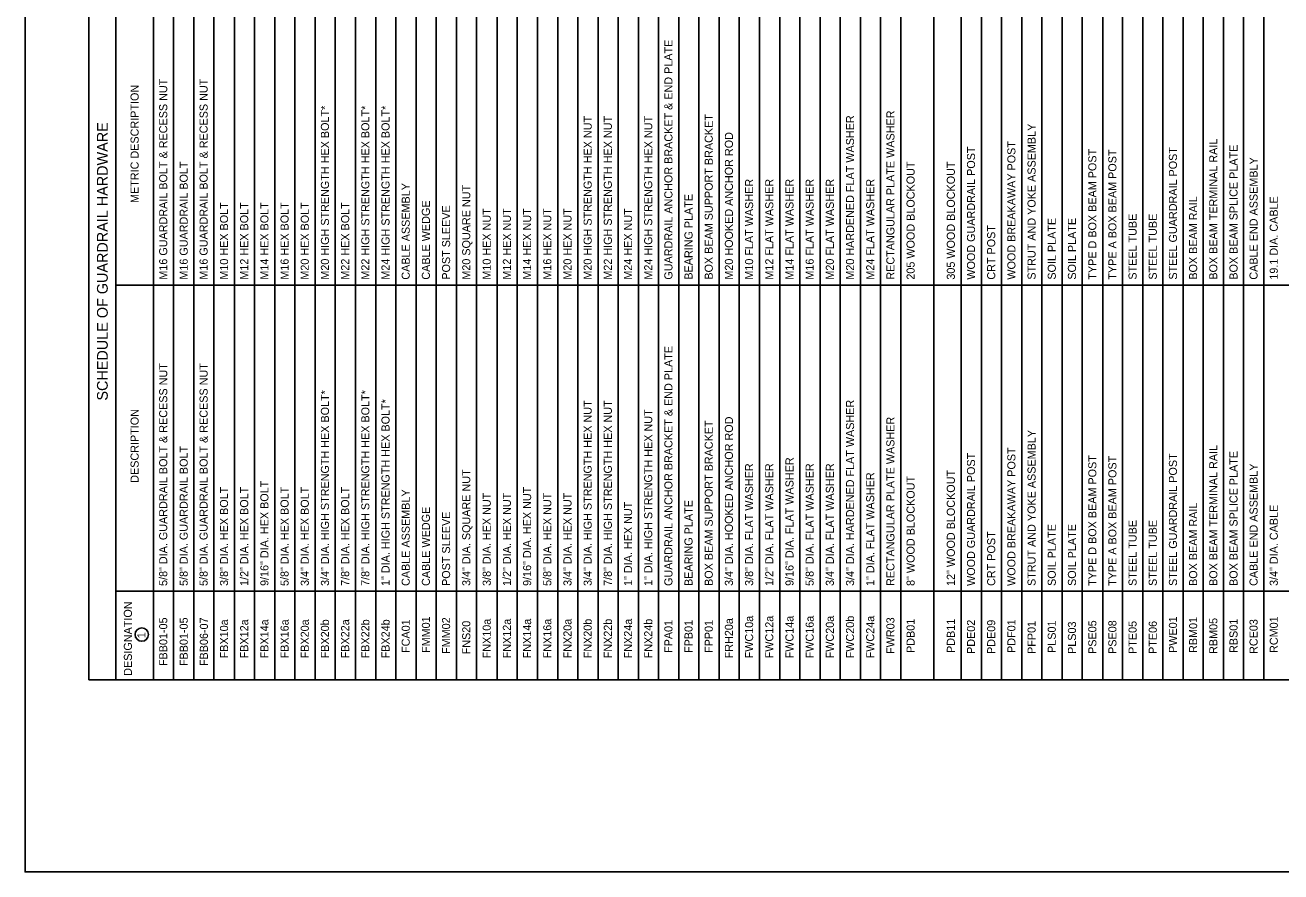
# Model space of a CAD drawing. Extents: x 49991.4 to 50021, y 49987.6 to 50011.4.
# Drawn here: x 49999.38 to 50008.71, y 49987.8 to 49994.09 of the extents above; entities that cross this region are included whole.
import ezdxf

# ---------------------------------------------------------------- set-up
doc = ezdxf.new("R2010")
doc.units = 0
doc.layers.add('Level 1', color=7, linetype='Continuous')
doc.layers.add('Level 2', color=7, linetype='Continuous')

msp = doc.modelspace()

# ---------------------------------------------------------------- linework, layer by layer
at = {"layer": 'Level 1'}
msp.add_lwpolyline([(49999.3755, 49998.9992), (50016.7421, 49998.9992), (50016.7421, 49987.7988), (49999.3755, 49987.7988)], close=True, dxfattribs=at)
at = {"layer": 'Level 2'}
for p, q in [((49999.8495, 49989.2267), (49999.8495, 49998.6426)), ((50000.3287, 49989.2267), (50000.3287, 49998.6426)), ((50000.4787, 49989.2267), (50000.4787, 49998.6426)), ((50000.6287, 49989.2267), (50000.6287, 49998.6426)), ((50000.7787, 49989.2267), (50000.7787, 49998.6426)), ((50000.9304, 49989.2267), (50000.9304, 49998.6426)), ((50001.0804, 49989.2267), (50001.0804, 49998.6426)), ((50001.2304, 49989.2267), (50001.2304, 49998.6426)), ((50001.3804, 49989.2267), (50001.3804, 49998.6426)), ((50001.5304, 49989.2267), (50001.5304, 49998.6426)), ((50001.6804, 49989.2267), (50001.6804, 49998.6426)), ((50001.8304, 49989.2267), (50001.8304, 49998.6426)), ((50001.9804, 49989.2267), (50001.9804, 49998.6426)), ((50002.1304, 49989.2267), (50002.1304, 49998.6426)), ((50002.2804, 49989.2267), (50002.2804, 49998.6426)), ((50002.4304, 49989.2267), (50002.4304, 49998.6426)), ((50002.5804, 49989.2267), (50002.5804, 49998.6426)), ((50002.7304, 49989.2267), (50002.7304, 49998.6426)), ((50002.8826, 49989.2267), (50002.8826, 49998.6426)), ((50003.0326, 49989.2267), (50003.0326, 49998.6426)), ((50003.1826, 49989.2267), (50003.1826, 49998.6426)), ((50003.3326, 49989.2267), (50003.3326, 49998.6426)), ((50003.4826, 49989.2267), (50003.4826, 49998.6426)), ((50003.6326, 49989.2267), (50003.6326, 49998.6426)), ((50003.7826, 49989.2267), (50003.7826, 49998.6426)), ((50003.9326, 49989.2267), (50003.9326, 49998.6426)), ((50004.0826, 49989.2267), (50004.0826, 49998.6426)), ((50004.2326, 49989.2267), (50004.2326, 49998.6426)), ((50004.3822, 49989.2267), (50004.3822, 49998.6426)), ((50004.5322, 49989.2267), (50004.5322, 49998.6426)), ((50004.6822, 49989.2267), (50004.6822, 49998.6426)), ((50004.8322, 49989.2267), (50004.8322, 49998.6426)), ((50004.9822, 49989.2267), (50004.9822, 49998.6426)), ((50005.1322, 49989.2267), (50005.1322, 49998.6426)), ((50005.2822, 49989.2267), (50005.2822, 49998.6426)), ((50005.4322, 49989.2267), (50005.4322, 49998.6426)), ((50005.5822, 49989.2267), (50005.5822, 49998.6426)), ((50005.7322, 49989.2267), (50005.7322, 49998.6426)), ((50005.8822, 49989.2267), (50005.8822, 49998.6426)), ((50006.1277, 49989.2267), (50006.1277, 49998.6426)), ((50006.3311, 49989.2267), (50006.3311, 49998.6426)), ((50006.4811, 49989.2267), (50006.4811, 49998.6426)), ((50006.6311, 49989.2267), (50006.6311, 49998.6426)), ((50006.7811, 49989.2267), (50006.7811, 49998.6426)), ((50006.9311, 49989.2267), (50006.9311, 49998.6426)), ((50007.0811, 49989.2267), (50007.0811, 49998.6426)), ((50007.2311, 49989.2267), (50007.2311, 49998.6426)), ((50007.3826, 49989.2267), (50007.3826, 49998.6426)), ((50007.5295, 49989.2267), (50007.5295, 49998.6426)), ((50007.6795, 49989.2267), (50007.6795, 49998.6426)), ((50007.8295, 49989.2267), (50007.8295, 49998.6426)), ((50007.9795, 49989.2267), (50007.9795, 49998.6426)), ((50008.1295, 49989.2267), (50008.1295, 49998.6426)), ((50008.2795, 49989.2267), (50008.2795, 49998.6426)), ((50008.4295, 49989.2267), (50008.4295, 49998.6426)), ((50008.5786, 49989.2267), (50008.5786, 49998.6426)), ((49999.8495, 49989.2267), (49999.8495, 49997.4312)), ((50000.0495, 49989.2267), (50000.0495, 49995.6426)), ((50000.0495, 49992.1605), (50013.2892, 49992.1605)), ((50013.2892, 49989.8841), (50000.0495, 49989.8841)), ((49999.8495, 49989.2267), (50013.2892, 49989.2267)), ((50000.6287, 49989.2267), (50000.4787, 49989.2267))]:
    msp.add_line(p, q, dxfattribs=at)
msp.add_circle((50000.2422, 49989.5627), 0.05, dxfattribs=at)

# ---------------------------------------------------------------- texts
for s, height, p in [('GUARDRAIL ANCHOR BRACKET & END PLATE', 0.06, (50004.1854, 49992.2005)), ('M16 GUARDRAIL BOLT & RECESS NUT', 0.06, (50000.4317, 49992.2004)), ('M16 GUARDRAIL BOLT & RECESS NUT', 0.06, (50000.7317, 49992.2004)), ('METRIC DESCRIPTION', 0.06, (50000.2191, 49992.7705)), ('M20 HIGH STRENGTH HEX BOLT*', 0.06, (50001.6334, 49992.2004)), ('M22 HIGH STRENGTH HEX BOLT*', 0.06, (50001.9334, 49992.2004)), ('M24 HIGH STRENGTH HEX BOLT*', 0.06, (50002.0834, 49992.2004)), ('M20 HIGH STRENGTH HEX NUT', 0.06, (50003.5854, 49992.2005)), ('M22 HIGH STRENGTH HEX NUT', 0.06, (50003.7354, 49992.2005)), ('M24 HIGH STRENGTH HEX NUT', 0.06, (50004.0354, 49992.2005)), ('BOX BEAM SUPPORT BRACKET', 0.06, (50004.485, 49992.2005)), ('M20 HARDENED FLAT WASHER', 0.06, (50005.535, 49992.2005)), ('RECTANGULAR PLATE WASHER', 0.06, (50005.835, 49992.2005)), ('SCHEDULE OF GUARDRAIL HARDWARE', 0.08, (49999.9895, 49991.3018)), ('M20 HOOKED ANCHOR ROD', 0.06, (50004.635, 49992.2005)), ('STRUT AND YOKE ASSEMBLY', 0.06, (50006.8839, 49992.2005)), ('WOOD BREAKAWAY POST', 0.06, (50006.7339, 49992.2005)), ('BOX BEAM TERMINAL RAIL', 0.06, (50008.2344, 49992.2005)), ('BOX BEAM SPLICE PLATE', 0.06, (50008.3844, 49992.2005)), ('WOOD GUARDRAIL POST', 0.06, (50006.4339, 49992.2005)), ('TYPE D BOX BEAM POST', 0.06, (50007.3354, 49992.2005)), ('TYPE A BOX BEAM POST', 0.06, (50007.4844, 49992.2005)), ('STEEL GUARDRAIL POST', 0.06, (50007.9344, 49992.2005)), ('CABLE END ASSEMBLY', 0.06, (50008.5335, 49992.2005)), ('M16 GUARDRAIL BOLT', 0.06, (50000.5837, 49992.2004)), ('205 WOOD BLOCKOUT', 0.06, (50005.985, 49992.2005)), ('305 WOOD BLOCKOUT', 0.06, (50006.2839, 49992.2005)), ('CABLE ASSEMBLY', 0.06, (50002.2334, 49992.2004)), ('M10 FLAT WASHER', 0.06, (50004.785, 49992.2005)), ('M12 FLAT WASHER', 0.06, (50004.935, 49992.2005)), ('M14 FLAT WASHER', 0.06, (50005.085, 49992.2005)), ('M16 FLAT WASHER', 0.06, (50005.235, 49992.2005)), ('M20 FLAT WASHER', 0.06, (50005.385, 49992.2005)), ('M24 FLAT WASHER', 0.06, (50005.685, 49992.2005)), ('M20 SQUARE NUT', 0.06, (50002.6834, 49992.2004)), ('BEARING PLATE', 0.06, (50004.335, 49992.2005)), ('M10 HEX BOLT', 0.06, (50000.8834, 49992.2004)), ('M12 HEX BOLT', 0.06, (50001.0334, 49992.2004)), ('M14 HEX BOLT', 0.06, (50001.1834, 49992.2004)), ('M16 HEX BOLT', 0.06, (50001.3334, 49992.2004)), ('M20 HEX BOLT', 0.06, (50001.4834, 49992.2004)), ('M22 HEX BOLT', 0.06, (50001.7834, 49992.2004)), ('CABLE WEDGE', 0.06, (50002.3834, 49992.2004)), ('POST SLEEVE', 0.06, (50002.5334, 49992.2004)), ('M10 HEX NUT', 0.06, (50002.8354, 49992.2005)), ('M12 HEX NUT', 0.06, (50002.9854, 49992.2005)), ('M14 HEX NUT', 0.06, (50003.1354, 49992.2005)), ('M16 HEX NUT', 0.06, (50003.2854, 49992.2005)), ('M20 HEX NUT', 0.06, (50003.4354, 49992.2005)), ('M24 HEX NUT', 0.06, (50003.8854, 49992.2005)), ('BOX BEAM RAIL', 0.06, (50008.0844, 49992.2005)), ('19.1 DIA. CABLE', 0.06, (50008.6835, 49992.2005)), ('SOIL PLATE', 0.06, (50007.0339, 49992.2005)), ('SOIL PLATE', 0.06, (50007.1839, 49992.2005)), ('STEEL TUBE', 0.06, (50007.6344, 49992.2005)), ('STEEL TUBE', 0.06, (50007.7844, 49992.2005)), ('CRT POST', 0.06, (50006.5839, 49992.2005)), ('GUARDRAIL ANCHOR BRACKET & END PLATE', 0.06, (50004.1854, 49989.9241)), ('5/8" DIA. GUARDRAIL BOLT & RECESS NUT', 0.06, (50000.4317, 49989.924)), ('5/8" DIA. GUARDRAIL BOLT & RECESS NUT', 0.06, (50000.7317, 49989.924)), ('3/4" DIA. HIGH STRENGTH HEX BOLT*', 0.06, (50001.6334, 49989.924)), ('7/8" DIA. HIGH STRENGTH HEX BOLT*', 0.06, (50001.9334, 49989.924)), ('1" DIA. HIGH STRENGTH HEX BOLT*', 0.06, (50002.0834, 49989.924)), ('3/4" DIA. HIGH STRENGTH HEX NUT', 0.06, (50003.5854, 49989.9241)), ('7/8" DIA. HIGH STRENGTH HEX NUT', 0.06, (50003.7354, 49989.9241)), ('1" DIA. HIGH STRENGTH HEX NUT', 0.06, (50004.0354, 49989.9241)), ('3/4" DIA. HARDENED FLAT WASHER', 0.06, (50005.535, 49989.9241)), ('DESCRIPTION', 0.06, (50000.2191, 49990.6907)), ('BOX BEAM SUPPORT BRACKET', 0.06, (50004.485, 49989.9241)), ('3/4" DIA. HOOKED ANCHOR ROD', 0.06, (50004.635, 49989.9241)), ('RECTANGULAR PLATE WASHER', 0.06, (50005.835, 49989.9241)), ('STRUT AND YOKE ASSEMBLY', 0.06, (50006.8839, 49989.9241)), ('5/8" DIA. GUARDRAIL BOLT', 0.06, (50000.5837, 49989.924)), ('BOX BEAM TERMINAL RAIL', 0.06, (50008.2344, 49989.9241)), ('9/16" DIA. FLAT WASHER', 0.06, (50005.085, 49989.9241)), ('WOOD GUARDRAIL POST', 0.06, (50006.4339, 49989.9241)), ('WOOD BREAKAWAY POST', 0.06, (50006.7339, 49989.9241)), ('TYPE D BOX BEAM POST', 0.06, (50007.3354, 49989.9241)), ('TYPE A BOX BEAM POST', 0.06, (50007.4844, 49989.9241)), ('STEEL GUARDRAIL POST', 0.06, (50007.9344, 49989.9241)), ('BOX BEAM SPLICE PLATE', 0.06, (50008.3844, 49989.9241)), ('3/4" DIA. SQUARE NUT', 0.06, (50002.6834, 49989.924)), ('3/8" DIA. FLAT WASHER', 0.06, (50004.785, 49989.9241)), ('1/2" DIA. FLAT WASHER', 0.06, (50004.935, 49989.9241)), ('5/8" DIA. FLAT WASHER', 0.06, (50005.235, 49989.9241)), ('3/4" DIA. FLAT WASHER', 0.06, (50005.385, 49989.9241)), ('12" WOOD BLOCKOUT', 0.06, (50006.2839, 49989.9241)), ('CABLE END ASSEMBLY', 0.06, (50008.5335, 49989.9241)), ('9/16" DIA. HEX BOLT', 0.06, (50001.1834, 49989.924)), ('1" DIA. FLAT WASHER', 0.06, (50005.685, 49989.9241)), ('8" WOOD BLOCKOUT', 0.06, (50005.985, 49989.9241)), ('3/8" DIA. HEX BOLT', 0.06, (50000.8834, 49989.924)), ('1/2" DIA. HEX BOLT', 0.06, (50001.0334, 49989.924)), ('5/8" DIA. HEX BOLT', 0.06, (50001.3334, 49989.924)), ('3/4" DIA. HEX BOLT', 0.06, (50001.4834, 49989.924)), ('7/8" DIA. HEX BOLT', 0.06, (50001.7834, 49989.924)), ('CABLE ASSEMBLY', 0.06, (50002.2334, 49989.924)), ('3/8" DIA. HEX NUT', 0.06, (50002.8354, 49989.9241)), ('1/2" DIA. HEX NUT', 0.06, (50002.9854, 49989.9241)), ('9/16" DIA. HEX NUT', 0.06, (50003.1354, 49989.9241)), ('5/8" DIA. HEX NUT', 0.06, (50003.2854, 49989.9241)), ('3/4" DIA. HEX NUT', 0.06, (50003.4354, 49989.9241)), ('CABLE WEDGE', 0.06, (50002.3834, 49989.924)), ('1" DIA. HEX NUT', 0.06, (50003.8854, 49989.9241)), ('BEARING PLATE', 0.06, (50004.335, 49989.9241)), ('BOX BEAM RAIL', 0.06, (50008.0844, 49989.9241)), ('3/4" DIA. CABLE', 0.06, (50008.6835, 49989.9241)), ('POST SLEEVE', 0.06, (50002.5334, 49989.924)), ('STEEL TUBE', 0.06, (50007.6344, 49989.9241)), ('STEEL TUBE', 0.06, (50007.7844, 49989.9241)), ('CRT POST', 0.06, (50006.5839, 49989.9241)), ('SOIL PLATE', 0.06, (50007.0339, 49989.9241)), ('SOIL PLATE', 0.06, (50007.1839, 49989.9241)), ('DESIGNATION', 0.06, (50000.1691, 49989.2562)), ('FBB01-05', 0.06, (50000.4317, 49989.3287)), ('FBB01-05', 0.06, (50000.5837, 49989.3287)), ('FBB06-07', 0.06, (50000.7337, 49989.3287)), ('FBX10a', 0.06, (50000.8834, 49989.3859)), ('FBX12a', 0.06, (50001.0334, 49989.3859)), ('FBX14a', 0.06, (50001.1834, 49989.3859)), ('FBX16a', 0.06, (50001.3334, 49989.3859)), ('FBX20a', 0.06, (50001.4834, 49989.3859)), ('FBX20b', 0.06, (50001.6334, 49989.3861)), ('FBX22a', 0.06, (50001.7834, 49989.3861)), ('FBX22b', 0.06, (50001.9334, 49989.3861)), ('FBX24b', 0.06, (50002.0834, 49989.3861)), ('FCA01', 0.06, (50002.2334, 49989.426)), ('FMM01', 0.06, (50002.3834, 49989.426)), ('FMM02', 0.06, (50002.5334, 49989.4187)), ('FNS20', 0.06, (50002.6834, 49989.4157)), ('FNX10a', 0.06, (50002.8354, 49989.386)), ('FNX12a', 0.06, (50002.9854, 49989.386)), ('FNX14a', 0.06, (50003.1354, 49989.386)), ('FNX16a', 0.06, (50003.2854, 49989.386)), ('FNX20a', 0.06, (50003.4354, 49989.386)), ('FNX20b', 0.06, (50003.5854, 49989.3862)), ('FNX22b', 0.06, (50003.7354, 49989.3862)), ('FNX24a', 0.06, (50003.8854, 49989.386)), ('FNX24b', 0.06, (50004.0354, 49989.386)), ('FPA01', 0.06, (50004.1854, 49989.4261)), ('FPB01', 0.06, (50004.335, 49989.4261)), ('FPP01', 0.06, (50004.485, 49989.4261)), ('FRH20a', 0.06, (50004.635, 49989.386)), ('FWC10a', 0.06, (50004.785, 49989.386)), ('FWC12a', 0.06, (50004.935, 49989.386)), ('FWC14a', 0.06, (50005.085, 49989.386)), ('FWC16a', 0.06, (50005.235, 49989.386)), ('FWC20a', 0.06, (50005.385, 49989.386)), ('FWC20b', 0.06, (50005.535, 49989.3862)), ('FWC24a', 0.06, (50005.685, 49989.386)), ('FWR03', 0.06, (50005.835, 49989.4188)), ('PDB01', 0.06, (50005.985, 49989.4261)), ('PDB11', 0.06, (50006.2839, 49989.4261)), ('PDE02', 0.06, (50006.4339, 49989.4188)), ('PDE09', 0.06, (50006.5839, 49989.4186)), ('PDF01', 0.06, (50006.7339, 49989.4261)), ('PFP01', 0.06, (50006.8839, 49989.4188)), ('PLS01', 0.06, (50007.0339, 49989.4261)), ('PLS03', 0.06, (50007.1839, 49989.4188)), ('PSE05', 0.06, (50007.3354, 49989.4188)), ('PSE08', 0.06, (50007.4844, 49989.4188)), ('PTE05', 0.06, (50007.6344, 49989.4188)), ('PTE06', 0.06, (50007.7844, 49989.4188)), ('PWE01', 0.06, (50007.9344, 49989.4261)), ('RBM01', 0.06, (50008.0844, 49989.4261)), ('RBM05', 0.06, (50008.2344, 49989.4188)), ('RBS01', 0.06, (50008.3844, 49989.4261)), ('RCE03', 0.06, (50008.5335, 49989.4188)), ('RCM01', 0.06, (50008.6835, 49989.4261)), ('1', 0.06, (50000.2691, 49989.5356))]:
    msp.add_text(s, height=height, rotation=90, dxfattribs=at).set_placement(p)

doc.saveas('drawing.dxf')
